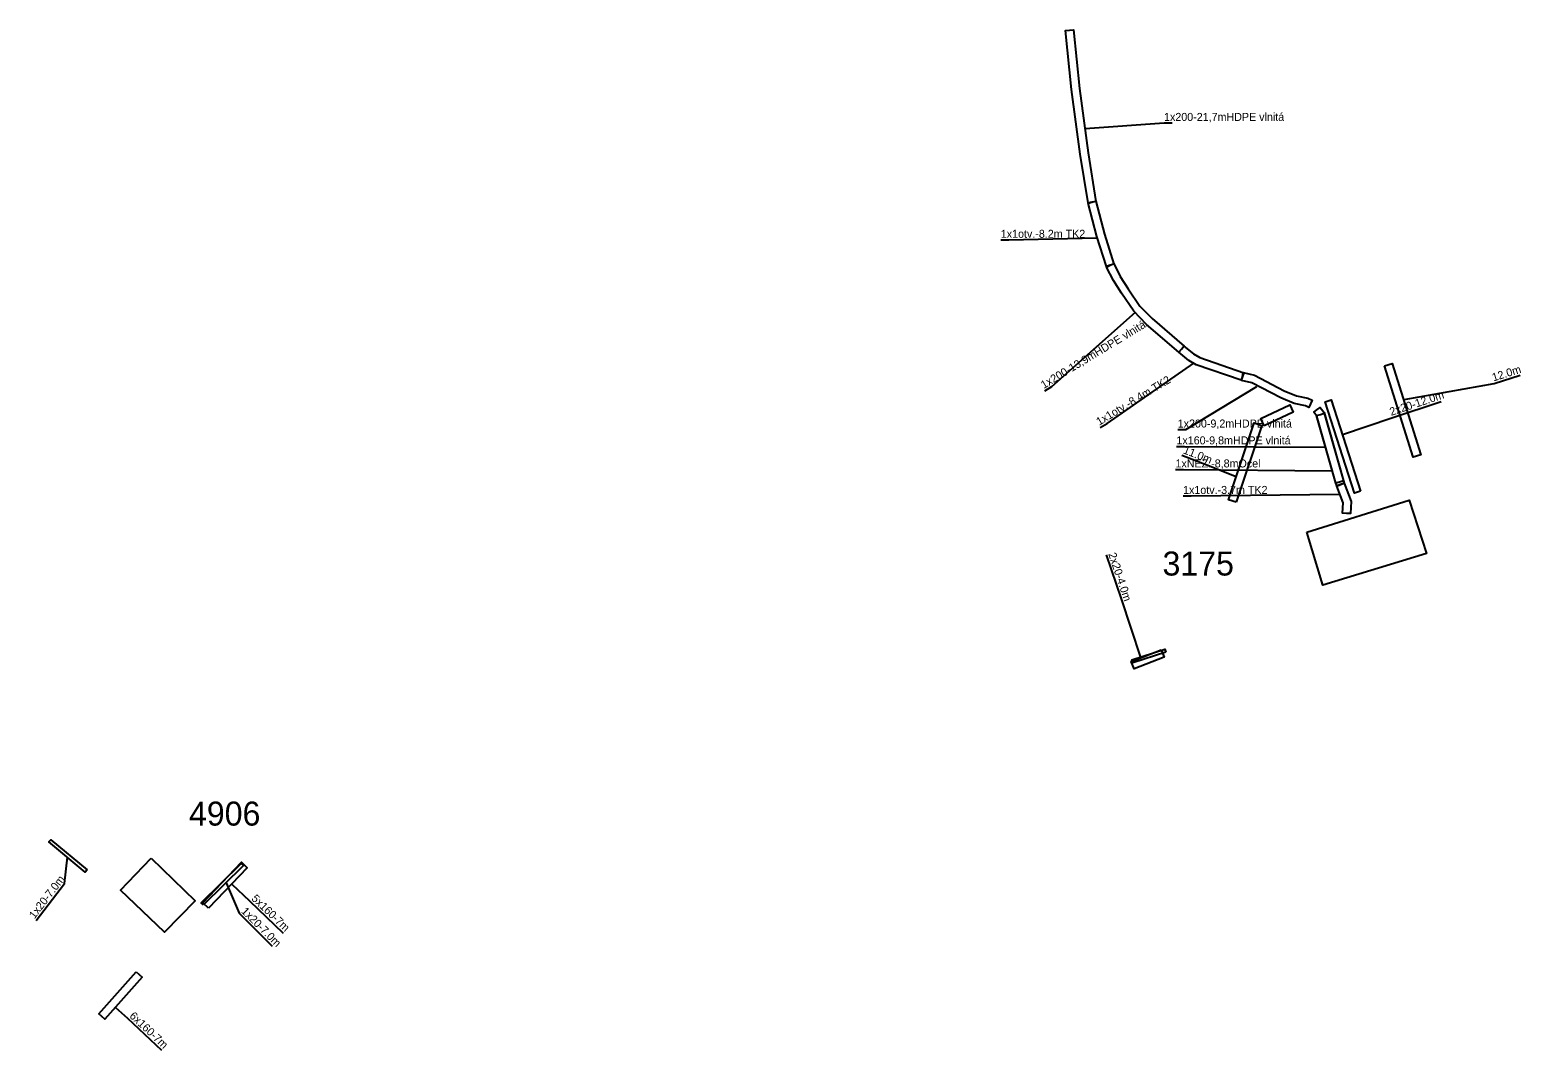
# Model space of a CAD drawing. Extents: x -743207 to -743021, y -1051356 to -1051229.
import ezdxf

# ---------------------------------------------------------------- set-up
doc = ezdxf.new("R2010")
doc.units = 0
for name, color, linetype in [('Chránička', 7, 'Continuous'), ('ST_CHRANICKA_POPIS', 7, 'Continuous'), ('ST_TRAFOSTANICE_POPIS', 7, 'Continuous'), ('TS_RS_R', 7, 'Continuous')]:
    doc.layers.add(name, color=color, linetype=linetype)

msp = doc.modelspace()

# ---------------------------------------------------------------- linework, layer by layer
at = {"layer": 'Chránička'}
for points in [[(-743074.628, -1051250.324), (-743075.122, -1051250.402), (-743076.082, -1051244.308), (-743077.188, -1051236.232), (-743077.915, -1051228.864), (-743077.417, -1051228.815), (-743076.919, -1051228.766), (-743076.194, -1051236.116), (-743075.092, -1051244.162), (-743074.134, -1051250.246), (-743074.628, -1051250.324)], [(-743072.35, -1051258.191), (-743072.826, -1051258.343), (-743074.017, -1051254.607), (-743075.112, -1051250.451), (-743074.628, -1051250.324), (-743074.144, -1051250.197), (-743073.057, -1051254.327), (-743071.874, -1051258.039), (-743072.35, -1051258.191)], [(-743063.445, -1051268.682), (-743063.771, -1051269.061), (-743067.791, -1051265.596), (-743069.412, -1051263.935), (-743070.951, -1051261.681), (-743071.955, -1051260.098), (-743072.797, -1051258.415), (-743072.35, -1051258.191), (-743071.903, -1051257.967), (-743071.083, -1051259.606), (-743070.115, -1051261.131), (-743068.636, -1051263.299), (-743067.105, -1051264.866), (-743063.119, -1051268.303), (-743063.445, -1051268.682)], [(-743055.82, -1051272.105), (-743055.984, -1051272.577), (-743061.585, -1051270.637), (-743062.52, -1051270.089), (-743063.762, -1051269.068), (-743063.445, -1051268.682), (-743063.128, -1051268.296), (-743061.946, -1051269.267), (-743061.165, -1051269.725), (-743055.656, -1051271.633), (-743055.82, -1051272.105)], [(-743038.064, -1051270.757), (-743037.11, -1051270.457), (-743033.511, -1051281.905), (-743034.465, -1051282.205), (-743038.064, -1051270.757)], [(-743047.301, -1051275.507), (-743047.513, -1051275.96), (-743047.947, -1051275.756), (-743049.373, -1051275.48), (-743051.027, -1051274.776), (-743054.647, -1051272.873), (-743055.927, -1051272.593), (-743055.82, -1051272.105), (-743055.713, -1051271.617), (-743054.301, -1051271.925), (-743050.597, -1051273.872), (-743049.079, -1051274.518), (-743047.635, -1051274.798), (-743047.089, -1051275.054), (-743047.301, -1051275.507)], [(-743053.102, -1051278.255), (-743053.526, -1051277.349), (-743049.904, -1051275.652), (-743049.48, -1051276.558), (-743053.102, -1051278.255)], [(-743043.563, -1051285.616), (-743044.036, -1051285.777), (-743044.149, -1051285.447), (-743046.531, -1051277.063), (-743046.904, -1051276.575), (-743046.507, -1051276.271), (-743046.11, -1051275.967), (-743045.621, -1051276.607), (-743043.193, -1051285.149), (-743043.09, -1051285.455), (-743043.563, -1051285.616)], [(-743041.045, -1051286.427), (-743041.806, -1051286.672), (-743045.49, -1051275.252), (-743044.729, -1051275.006), (-743041.045, -1051286.427)], [(-743056.611, -1051287.829), (-743057.559, -1051287.511), (-743054.345, -1051277.904), (-743053.397, -1051278.222), (-743056.611, -1051287.829)], [(-743043.671, -1051285.298), (-743044.152, -1051285.435), (-743046.557, -1051276.972), (-743046.076, -1051276.835), (-743045.595, -1051276.698), (-743043.19, -1051285.161), (-743043.671, -1051285.298)], [(-743042.794, -1051289.206), (-743043.294, -1051289.185), (-743043.239, -1051287.891), (-743044.031, -1051285.793), (-743043.563, -1051285.616), (-743043.095, -1051285.439), (-743042.231, -1051287.729), (-743042.294, -1051289.227), (-743042.794, -1051289.206)], [(-743065.989, -1051306.253), (-743065.623, -1051307.183), (-743069.346, -1051308.646), (-743069.712, -1051307.716), (-743065.989, -1051306.253)], [(-743065.388, -1051306.553), (-743069.514, -1051307.886), (-743069.637, -1051307.506), (-743065.51, -1051306.173), (-743065.388, -1051306.553)], [(-743200.224, -1051333.749), (-743200.479, -1051334.057), (-743205.002, -1051330.259), (-743204.77, -1051330.003), (-743200.224, -1051333.749)], [(-743185.679, -1051338.161), (-743185.959, -1051337.877), (-743180.976, -1051332.961), (-743180.695, -1051333.245), (-743185.679, -1051338.161)], [(-743185.054, -1051338.576), (-743185.776, -1051337.886), (-743180.939, -1051332.826), (-743180.217, -1051333.516), (-743185.054, -1051338.576)], [(-743194.094, -1051346.529), (-743193.348, -1051347.195), (-743198.007, -1051352.419), (-743198.753, -1051351.753), (-743194.094, -1051346.529)]]:
    msp.add_lwpolyline(points, close=True, dxfattribs=at)
at = {"layer": 'ST_CHRANICKA_POPIS'}
for points in [[(-743075.456, -1051241.096), (-743065.618, -1051240.403), (-743064.618, -1051240.403)], [(-743086.022, -1051255.013), (-743085.022, -1051255.013), (-743074.02, -1051254.751)], [(-743080.517, -1051273.885), (-743079.661, -1051273.367), (-743069.204, -1051264.059)], [(-743073.591, -1051278.476), (-743072.736, -1051277.958), (-743061.88, -1051270.429)], [(-743035.585, -1051274.962), (-743024.369, -1051272.962), (-743021.093, -1051271.939)], [(-743063.907, -1051278.728), (-743062.907, -1051278.728), (-743054.014, -1051273.345)], [(-743043.332, -1051279.354), (-743037.153, -1051277.262), (-743030.962, -1051275.218)], [(-743064.065, -1051280.834), (-743063.065, -1051280.834), (-743045.425, -1051280.934)], [(-743063.394, -1051281.917), (-743060.281, -1051283.125), (-743056.615, -1051284.584)], [(-743064.187, -1051283.716), (-743063.187, -1051283.716), (-743044.647, -1051283.875)], [(-743063.239, -1051287.029), (-743062.239, -1051287.029), (-743043.683, -1051286.828)], [(-743072.837, -1051294.381), (-743070.981, -1051299.911), (-743068.556, -1051307.246)], [(-743206.598, -1051340.113), (-743203.046, -1051335.486), (-743202.684, -1051332.184)], [(-743182.862, -1051335.385), (-743181.213, -1051339.203), (-743177.089, -1051343.329)], [(-743182.144, -1051335.564), (-743179.936, -1051337.632), (-743175.725, -1051341.669)], [(-743196.658, -1051350.98), (-743195.179, -1051352.32), (-743190.924, -1051356.311)]]:
    msp.add_lwpolyline(points, dxfattribs=at)
at = {"layer": 'TS_RS_R'}
for points in [[(-743047.75, -1051291.56), (-743034.97, -1051287.57), (-743032.83, -1051294.22), (-743045.79, -1051298.2), (-743047.75, -1051291.56)], [(-743192.21, -1051332.32), (-743186.73, -1051337.64), (-743190.57, -1051341.56), (-743196.07, -1051336.3), (-743192.21, -1051332.32)]]:
    msp.add_lwpolyline(points, close=True, dxfattribs=at)

# ---------------------------------------------------------------- texts
at = {"layer": 'ST_CHRANICKA_POPIS'}
for s, p in [('1x200-21,7mHDPE vlnitá', (-743065.618, -1051240.153)), ('1x1otv.-8.2m TK2', (-743086.022, -1051254.763)), ('1x200-9,2mHDPE vlnitá', (-743063.907, -1051278.478)), ('1x160-9,8mHDPE vlnitá', (-743064.065, -1051280.584)), ('1xNEZ.-8,8mOcel', (-743064.187, -1051283.466)), ('1x1otv.-3.7m TK2', (-743063.239, -1051286.779))]:
    msp.add_text(s, height=1, dxfattribs=at).set_placement(p)
for s, rotation, p in [('1x200-13,9mHDPE vlnitá', 31.18852, (-743080.646, -1051273.671)), ('1x1otv.-8.4m TK2', 31.19038, (-743073.721, -1051278.262)), ('12.0m', 17.33975, (-743024.444, -1051272.723)), ('2x20-12.0m', 18.26805, (-743037.232, -1051277.024)), ('11.0m', 338.79592, (-743063.304, -1051281.684)), ('2x20-4.0m', 288.55254, (-743072.6, -1051294.301)), ('1x20-7.0m', 52.48456, (-743206.797, -1051339.961)), ('5x160-7m', 316.21199, (-743179.763, -1051337.452)), ('1x20-7.0m', 314.99523, (-743181.036, -1051339.027)), ('6x160-7m', 316.83205, (-743195.008, -1051352.138))]:
    msp.add_text(s, height=1, rotation=rotation, dxfattribs=at).set_placement(p)
at = {"layer": 'ST_TRAFOSTANICE_POPIS'}
for s, p in [('3175', (-743065.808, -1051296.981)), ('4906', (-743187.49, -1051328.239))]:
    msp.add_text(s, height=3, dxfattribs=at).set_placement(p)

doc.saveas('drawing.dxf')
